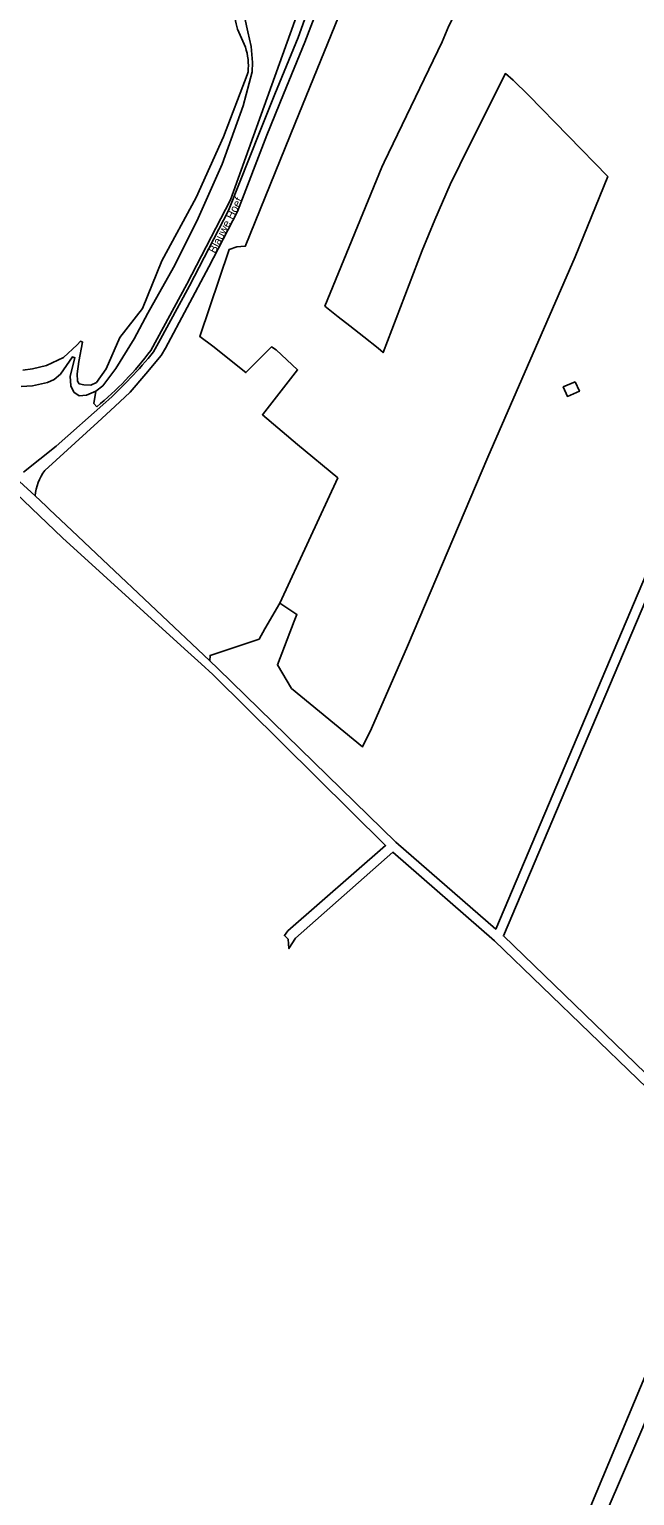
# Model space of a CAD drawing. Extents: x 135990 to 139000, y 393500 to 396000.
# Drawn here: x 136437.3 to 136626.3, y 393970.7 to 394428.9 of the extents above; entities that cross this region are included whole.
import ezdxf

# ---------------------------------------------------------------- set-up
doc = ezdxf.new("R2010")
doc.units = 0
doc.layers.add('gg-anno-openbare ruimte label', color=7, linetype='Continuous')
doc.layers.add('gx-grn-maaiveld', color=7, linetype='Continuous')

msp = doc.modelspace()

# ---------------------------------------------------------------- linework, layer by layer
at = {"layer": 'gx-grn-maaiveld'}
msp.add_line((136504.735, 394423.344), (136502.271, 394428.882), dxfattribs=at)
for points in [[(136537.656, 394476.745), (136531.593, 394463.556), (136500.054, 394375.566), (136486.473, 394349.21), (136475.224, 394328.55)], [(136531.066, 394447.263), (136527.559, 394435.978), (136523.316, 394424.855), (136516.606, 394408.614), (136511.475, 394395.788), (136502.253, 394371.931), (136493.306, 394354.666), (136479.803, 394329.209), (136478.435, 394326.966), (136473.627, 394321.224), (136468.8, 394315.492), (136464.02, 394311.071), (136458.695, 394306.145), (136442.108, 394291.057)], [(136538.356, 394444.09), (136539.542, 394446.721), (136551.249, 394442.109), (136570.766, 394434.849), (136568.278, 394429.958), (136566.15, 394424.947), (136548.057, 394387.386)], [(136538.356, 394444.09), (136520.317, 394399.613), (136504.674, 394361.046), (136504.534, 394361.126), (136502.073, 394360.967), (136499.692, 394360.094), (136490.484, 394332.868), (136494.631, 394329.851), (136504.917, 394321.606), (136512.948, 394329.661), (136514.384, 394328.69), (136521.044, 394322.47), (136510.064, 394308.477), (136520.98, 394299.18), (136533.6, 394288.739), (136515.551, 394249.626)], [(136476.091, 394328.078), (136477.603, 394330.935), (136487.317, 394348.775), (136499.449, 394372.319), (136509.374, 394397.18), (136513.914, 394408.591), (136521.228, 394426.287), (136524.753, 394436.249)], [(136458.019, 394315.845), (136460.26, 394317.522), (136464.34, 394322.907), (136470.032, 394332.214), (136474.269, 394340.208), (136482.349, 394354.512), (136489.595, 394368.916), (136497.49, 394386.772), (136504.073, 394405.002), (136506.86, 394415.568), (136506.968, 394418.532), (136506.531, 394423.475), (136505.558, 394428.105), (136504.562, 394432.327)], [(136505.582, 394415.571), (136505.263, 394414.653), (136497.943, 394395.25), (136489.424, 394376.331), (136478.692, 394356.531), (136472.611, 394341.696), (136465.589, 394332.633), (136461.287, 394322.848), (136458.206, 394318.579), (136456.488, 394317.713), (136454.344, 394317.799), (136452.817, 394318.143), (136452.277, 394318.935), (136452.248, 394321.263), (136452.708, 394325.097), (136453.91, 394331.159), (136453.304, 394331.428), (136452.188, 394330.252), (136448.001, 394326.325), (136442.625, 394323.851), (136438.224, 394322.751), (136435.253, 394322.361)], [(136548.057, 394387.386), (136547.369, 394385.834), (136529.602, 394342.416), (136533.733, 394339.027), (136537.369, 394336.189), (136541.715, 394332.818), (136546.194, 394329.271), (136547.746, 394327.852), (136559.897, 394359.825), (136563.888, 394369.315), (136568.677, 394380.402), (136574.708, 394392.73), (136585.928, 394415.036), (136588.367, 394412.996), (136593.112, 394408.34), (136617.922, 394382.939), (136607.74, 394357.759), (136580.488, 394295.185), (136555.352, 394236.183), (136544.107, 394210.387), (136541.329, 394204.698), (136519.104, 394222.954), (136514.738, 394230.363), (136520.03, 394243.988), (136520.85, 394246.049), (136517.369, 394248.295), (136515.551, 394249.626)], [(136384.606, 394330.258), (136447.68, 394269.954), (136485.761, 394235.27), (136490.915, 394230.576), (136494.53, 394227.283), (136548.534, 394173.838), (136517.98, 394147.183), (136516.938, 394145.729), (136518.069, 394144.598), (136518.361, 394141.631), (136520.434, 394144.954), (136550.745, 394171.773), (136582.535, 394144.116), (136656.951, 394072.245), (136651.451, 394059.845), (136635.624, 394022.487), (136610.7, 393963.041)], [(136434.778, 394317.239), (136438.226, 394317.463), (136442.91, 394318.489), (136445.072, 394319.493), (136446.972, 394321.162), (136450.77, 394326.575), (136451.519, 394326.285), (136450.06, 394320.531), (136450.225, 394317.521), (136451.177, 394315.52), (136452.85, 394314.416), (136455.126, 394314.566), (136458.019, 394315.845)], [(136607.719, 394318.776), (136609.025, 394315.808), (136605.299, 394314.168), (136603.992, 394317.136), (136607.719, 394318.776)], [(136435.505, 394290.499), (136445.623, 394298.606), (136461.148, 394312.346)], [(136458.019, 394315.845), (136457.42, 394311.974), (136458.341, 394310.933)], [(136493.645, 394231.52), (136496.17, 394229.133), (136551.754, 394174.872), (136582.945, 394147.736), (136649.09, 394303.798), (136651.852, 394302.627), (136585.303, 394145.611), (136658.246, 394075.165), (136693.621, 394154.925), (136698.479, 394153.533), (136659.101, 394063.24), (136627.918, 393989.815), (136591.541, 393905.23), (136555.637, 393822.291), (136533.435, 393771.894), (136532.72, 393766.839), (136532.593, 393762.254), (136564.257, 393720.1)], [(136432.645, 394289.115), (136434.253, 394287.602), (136439.069, 394283.071)], [(136493.645, 394231.52), (136460.147, 394263.198), (136452.456, 394270.471), (136443.426, 394278.972), (136442.49, 394279.853), (136439.069, 394283.071)], [(136515.551, 394249.626), (136510.806, 394241.555), (136509.032, 394238.317), (136493.747, 394233.234), (136493.645, 394231.52)]]:
    msp.add_lwpolyline(points, dxfattribs=at)
for centre, radius, start, end in [((136522.503, 394434.73), 21.06, 176.68009, 196.12306), ((136487.278, 394417.509), 18.407, 353.95603, 18.48159), ((136391.142, 394392.231), 105.475, 309.57652, 322.86109), ((136351.736, 394431.234), 161.571, 312.62333, 320.32346), ((136454.926, 394281.608), 15.924, 143.60374, 174.72852)]:
    msp.add_arc(centre, radius, start, end, dxfattribs=at)

# ---------------------------------------------------------------- texts
at = {"layer": 'gg-anno-openbare ruimte label'}
msp.add_text('Blauwe Hoef', height=2.5, rotation=62.7, dxfattribs=at).set_placement((136495.309, 394358.671))

doc.saveas('drawing.dxf')
